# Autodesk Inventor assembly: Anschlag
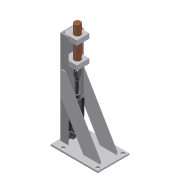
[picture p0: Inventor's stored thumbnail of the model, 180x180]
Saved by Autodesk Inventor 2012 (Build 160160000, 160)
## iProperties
Company: CAD-Verlag
Created: 2004-09
Part Number: Anschlag
Document SubType Name: Assembly
Designer: Greiling
Manufacturer: Standard
Standards Organization: Custom
Checked By: Jürgen Kronas
Stock Number: 10-10007
Author: Juergen Kronas
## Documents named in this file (11)
- C:\Daten Vault 2012 Inventor\Kapitel 6\6.2\Anschlag\Anschlag.iam
- C:\Daten Vault 2012 Inventor\Kapitel 6\6.2\Anschlag\Ständer.iam
- C:\Daten Vault 2012 Inventor\Kapitel 6\6.2\Anschlag\local.DIN.37.480.8.ipt
- C:\Daten Vault 2012 Inventor\Kapitel 6\6.2\Anschlag\Bolzenführung.iam
- C:\Daten Vault 2012 Inventor\Kapitel 6\6.2\Anschlag\Anschlag_Rund.ipt
- C:\Daten Vault 2012 Inventor\Kapitel 6\6.2\Anschlag\532740_DNCB_40_80_PPV_A_1.iam
- C:\Daten Vault 2012 Inventor\Kapitel 6\6.2\Anschlag\LNG_40.ipt
- C:\Daten Vault 2012 Inventor\Kapitel 6\6.2\Anschlag\SG_M12.ipt
- C:\Daten Vault 2012 Inventor\Kapitel 6\6.2\Anschlag\SNCB_40.ipt
- C:\Daten Vault 2012 Inventor\Kapitel 6\6.2\Anschlag\local.DIN.179.11.8.ipt
- C:\Daten Vault 2012 Inventor\Kapitel 6\6.2\Anschlag\local.DIN.19.192.8.ipt
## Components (20 placed, 10 different names)
1. Ständer:1 [sub-assembly] — Passend:1, Passend:2, Passend:3, Passend:4, Passend:5, Passend:8, Passend:9, Passend:10, Passend:15, Passend:17, Passend:20, Passend:21, Einfügen:2, Einfügen:3, Einfügen:5
2. Bolzenführung:1 [sub-assembly] — Passend:4, Passend:5, Passend:6
3. Bolzenführung:2 [sub-assembly] — Passend:1, Passend:2, Passend:3, Passend:6, Passend:7
4. Anschlag_Rund:1 — Passend:7, Passend:15, Passend:16
5. 532740_DNCB_40_80_PPV_A_1:1 [sub-assembly] — Passend:11, Passend:12, Passend:13, Passend:18, Passend:19
6. LNG_40:1 — Passend:11, Passend:12, Passend:13, Passend:14
7. SG_M12:1 — Passend:16, Passend:17, Passend:18, Passend:19
8. SNCB_40:1 — Passend:8, Passend:9, Passend:10, Passend:14, Einfügen:4
9. DIN 912  (Regelgewinde) - ersetzt durch DIN EN ISO 4762 M4 x 10:1 — Einfügen:2
10. DIN 912  (Regelgewinde) - ersetzt durch DIN EN ISO 4762 M4 x 10:2 — Einfügen:3
11. DIN 912  (Regelgewinde) - ersetzt durch DIN EN ISO 4762 M4 x 10:3 — Einfügen:4
12. DIN 912  (Regelgewinde) - ersetzt durch DIN EN ISO 4762 M4 x 10:4 — Einfügen:5
13. DIN 127 - zurückgezogen A 10:1 — Passend:20, Passend:21, Einfügen:1
14. DIN 933  (Regelgewinde) - ersetzt durch DIN EN 24 017 M10  x 25:1 — Einfügen:1
15. DIN 127 - zurückgezogen A 10:2
16. DIN 933  (Regelgewinde) - ersetzt durch DIN EN 24 017 M10  x 25:2
17. DIN 127 - zurückgezogen A 10:3
18. DIN 933  (Regelgewinde) - ersetzt durch DIN EN 24 017 M10  x 25:3
19. DIN 127 - zurückgezogen A 10:4
20. DIN 933  (Regelgewinde) - ersetzt durch DIN EN 24 017 M10  x 25:4
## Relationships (26: Mate 21, Insert 5)
- Passend:1 [Mate]: Ständer:1 ↔ Bolzenführung:2
- Passend:2 [Mate]: Ständer:1 ↔ Bolzenführung:2
- Passend:3 [Mate]: Ständer:1 ↔ Bolzenführung:2
- Passend:4 [Mate]: Ständer:1 ↔ Bolzenführung:1
- Passend:5 [Mate]: Ständer:1 ↔ Bolzenführung:1
- Passend:6 [Mate]: Bolzenführung:1 ↔ Bolzenführung:2
- Passend:7 [Mate]: Bolzenführung:2 ↔ Anschlag_Rund:1
- Passend:8 [Mate]: Ständer:1 ↔ SNCB_40:1
- Passend:9 [Mate]: Ständer:1 ↔ SNCB_40:1
- Passend:10 [Mate]: Ständer:1 ↔ SNCB_40:1
- Passend:11 [Mate]: 532740_DNCB_40_80_PPV_A_1:1 ↔ LNG_40:1
- Passend:12 [Mate]: 532740_DNCB_40_80_PPV_A_1:1 ↔ LNG_40:1
- Passend:13 [Mate]: 532740_DNCB_40_80_PPV_A_1:1 ↔ LNG_40:1
- Passend:14 [Mate]: LNG_40:1 ↔ SNCB_40:1
- Passend:15 [Mate]: Ständer:1 ↔ Anschlag_Rund:1
- Passend:16 [Mate]: Anschlag_Rund:1 ↔ SG_M12:1
- Passend:17 [Mate]: Ständer:1 ↔ SG_M12:1
- Passend:18 [Mate]: 532740_DNCB_40_80_PPV_A_1:1 ↔ SG_M12:1
- Passend:19 [Mate]: 532740_DNCB_40_80_PPV_A_1:1 ↔ SG_M12:1
- Passend:20 [Mate]: Ständer:1 ↔ DIN 127 - zurückgezogen A 10:1
- Passend:21 [Mate]: Ständer:1 ↔ DIN 127 - zurückgezogen A 10:1
- Einfügen:1 [Insert]: DIN 127 - zurückgezogen A 10:1 ↔ DIN 933  (Regelgewinde) - ersetzt durch DIN EN 24 017 M10  x 25:1
- Einfügen:2 [Insert]: Ständer:1 ↔ DIN 912  (Regelgewinde) - ersetzt durch DIN EN ISO 4762 M4 x 10:1
- Einfügen:3 [Insert]: Ständer:1 ↔ DIN 912  (Regelgewinde) - ersetzt durch DIN EN ISO 4762 M4 x 10:2
- Einfügen:5 [Insert]: Ständer:1 ↔ DIN 912  (Regelgewinde) - ersetzt durch DIN EN ISO 4762 M4 x 10:4
- Einfügen:4 [Insert]: SNCB_40:1 ↔ DIN 912  (Regelgewinde) - ersetzt durch DIN EN ISO 4762 M4 x 10:3
